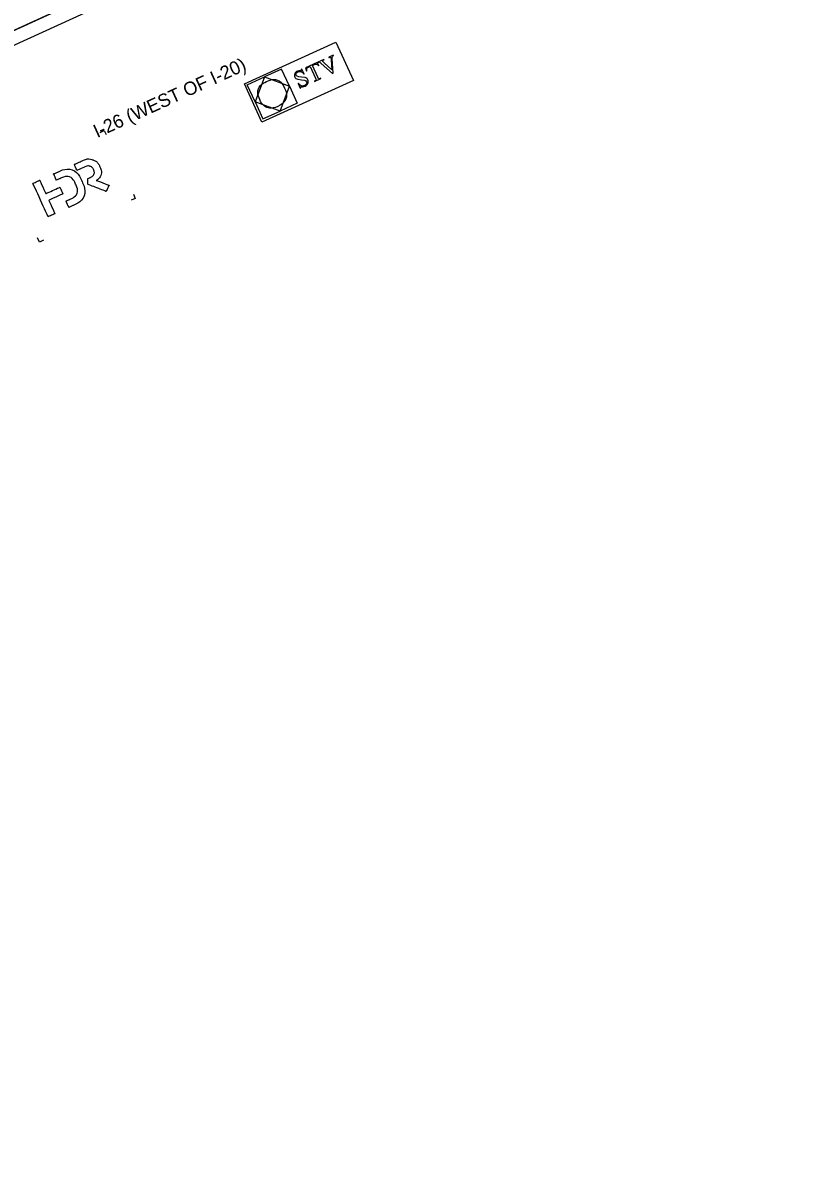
# Model space of a CAD drawing. Extents: x 1952253 to 1982336, y 791177 to 808695.
# Drawn here: x 1973525 to 1979258, y 791177 to 799664 of the extents above; entities that cross this region are included whole.
import ezdxf

# ---------------------------------------------------------------- set-up
doc = ezdxf.new("R2010")
doc.units = 0
for name, color, linetype in [('RD_SHT_Bndy', 7, 'Continuous'), ('RD_SHT_IplotShp', 7, 'Continuous'), ('RD_SHT_Misc2', 7, 'Continuous'), ('RD_SHT_Misc4', 7, 'Continuous'), ('RD_SHT_TX', 7, 'Continuous')]:
    doc.layers.add(name, color=color, linetype=linetype)

msp = doc.modelspace()

# ---------------------------------------------------------------- linework, layer by layer
at = {"layer": 'RD_SHT_Bndy'}
for points in [[(1979125.3, 802195.5), (1955294.1, 791309), (1952385.5, 797676.1), (1976216.7, 808562.6)], [(1959270.9, 793125.7), (1973897.5, 799807.4), (1973461.2, 800762.4), (1958834.7, 794080.8)]]:
    msp.add_lwpolyline(points, close=True, dxfattribs=at)
at = {"layer": 'RD_SHT_IplotShp'}
msp.add_lwpolyline([(1979257.8, 802146.1), (1955244.7, 791176.5), (1952253, 797725.5), (1976266.1, 808695.1)], close=True, dxfattribs=at)
at = {"layer": 'RD_SHT_Misc2'}
for points in [[(1974102.6, 798845.3), (1974133.3, 798859.3), (1974147.3, 798828.6)], [(1974350.4, 798384.1), (1974364.4, 798353.4), (1974333.7, 798339.4)], [(1973680.7, 798041.1), (1973650.1, 798027.1), (1973636, 798057.8)]]:
    msp.add_lwpolyline(points, dxfattribs=at)
for points in [[(1973930.1, 798561.3), (1973930.1, 798561.3), (1973986.4, 798587), (1973986.4, 798587), (1973986.4, 798587), (1974003.4, 798594.8), (1974016.6, 798596.5), (1974028.6, 798592.1), (1974028.6, 798592.1), (1974039.6, 798588.1), (1974048, 798580.1), (1974053.1, 798569), (1974053.1, 798569), (1974064.6, 798543.8), (1974049.7, 798518.8), (1974025.4, 798507.7), (1974025.4, 798507.7), (1974025.4, 798507.7), (1974011.4, 798501.3), (1974011.4, 798501.3), (1974011.4, 798501.3), (1974011.4, 798501.3), (1974011.1, 798458.1), (1974011.1, 798458.1), (1974011.1, 798458.1), (1974011.1, 798458.1), (1974147, 798404.6), (1974147, 798404.6), (1974147, 798404.6), (1974147, 798404.6), (1974169.2, 798451.1), (1974169.2, 798451.1), (1974169.2, 798451.1), (1974169.2, 798451.1), (1974073.6, 798487.2), (1974073.6, 798487.2), (1974073.6, 798487.2), (1974106.7, 798510.4), (1974116.2, 798554.7), (1974100.4, 798589.4), (1974100.4, 798589.4), (1974088.5, 798615.5), (1974071.9, 798632.1), (1974045.4, 798641.1), (1974045.4, 798641.1), (1974017.9, 798650.4), (1973994.6, 798645), (1973962.4, 798630.3), (1973962.4, 798630.3), (1973962.4, 798630.3), (1973909.5, 798606.2), (1973909.5, 798606.2), (1973909.5, 798606.2), (1973909.5, 798606.2), (1973930.1, 798561.3), (1973930.1, 798561.3)], [(1973966.6, 798481.5), (1973966.6, 798481.5), (1973966.5, 798481.6), (1973966.5, 798481.6), (1973966.5, 798481.6), (1973966.5, 798481.6), (1973966.5, 798481.6), (1973966.5, 798481.6), (1973966.5, 798481.6), (1973933.4, 798553.8), (1973857, 798582.2), (1973784.7, 798549.2), (1973784.7, 798549.2), (1973784.7, 798549.2), (1973755.2, 798535.7), (1973755.2, 798535.7), (1973755.2, 798535.7), (1973755.2, 798535.7), (1973776.6, 798488.8), (1973776.6, 798488.8), (1973776.6, 798488.8), (1973776.6, 798488.8), (1973806.1, 798502.3), (1973806.1, 798502.3), (1973806.1, 798502.3), (1973852, 798523.2), (1973898.7, 798505.9), (1973919.7, 798460.1), (1973919.7, 798460.1), (1973940.5, 798414.2), (1973923.2, 798367.3), (1973877.4, 798346.3), (1973877.4, 798346.3), (1973877.4, 798346.3), (1973847.8, 798332.8), (1973847.8, 798332.8), (1973847.8, 798332.8), (1973847.8, 798332.8), (1973869.3, 798286), (1973869.3, 798286), (1973869.3, 798286), (1973869.3, 798286), (1973898.8, 798299.4), (1973898.8, 798299.4), (1973898.8, 798299.4), (1973971, 798332.5), (1973999.4, 798409.1), (1973966.6, 798481.4), (1973966.6, 798481.4), (1973966.6, 798481.4), (1973966.6, 798481.4), (1973966.6, 798481.4), (1973966.6, 798481.4), (1973966.6, 798481.4), (1973966.6, 798481.5), (1973966.6, 798481.5)], [(1973802.1, 798436.4), (1973802.1, 798436.4), (1973697.1, 798388.4), (1973697.1, 798388.4), (1973697.1, 798388.4), (1973697.1, 798388.4), (1973651.5, 798488.3), (1973651.5, 798488.3), (1973651.5, 798488.3), (1973651.5, 798488.3), (1973600.8, 798465.2), (1973600.8, 798465.2), (1973600.8, 798465.2), (1973600.8, 798465.2), (1973714.9, 798215.5), (1973714.9, 798215.5), (1973714.9, 798215.5), (1973714.9, 798215.5), (1973765.5, 798238.6), (1973765.5, 798238.6), (1973765.5, 798238.6), (1973765.5, 798238.6), (1973719.9, 798338.5), (1973719.9, 798338.5), (1973719.9, 798338.5), (1973719.9, 798338.5), (1973824.9, 798386.5), (1973824.9, 798386.5), (1973824.9, 798386.5), (1973824.9, 798386.5), (1973802.1, 798436.4), (1973802.1, 798436.4)]]:
    msp.add_open_spline(points, degree=3, dxfattribs=at)
at = {"layer": 'RD_SHT_Misc4'}
for points in [[(1975178.8, 799208.1), (1975860.9, 799519.7), (1975991.7, 799233.5), (1975309.5, 798921.8)], [(1975841.2, 799421.6), (1975808.2, 799406.5), (1975809.2, 799404.3), (1975810.7, 799404.6), (1975815.9, 799405.6), (1975819.9, 799405.2), (1975824.3, 799401.8), (1975826.4, 799387.2), (1975831.3, 799313.4), (1975773.6, 799364), (1975764.3, 799374.9), (1975763.6, 799377.7), (1975764.3, 799380.6), (1975767.2, 799383.8), (1975772.9, 799387.7), (1975771.8, 799389.9), (1975726.7, 799369.3), (1975727.7, 799367), (1975736.5, 799368.6), (1975743.3, 799366.6), (1975752, 799359.1), (1975836.8, 799284.6), (1975841, 799286.5), (1975833.9, 799394.8), (1975833.8, 799404.1), (1975835.4, 799411.3), (1975837.9, 799415.4), (1975842.3, 799419.4)], [(1975607.6, 799317.6), (1975605.2, 799316.6), (1975605.6, 799310.1), (1975602.7, 799307.1), (1975595.1, 799306.4), (1975583.9, 799305.4), (1975574.2, 799302.4), (1975567.5, 799298.7), (1975562.2, 799294.3), (1975557.7, 799289.1), (1975554.6, 799283.1), (1975552.6, 799276.8), (1975551.9, 799270.7), (1975552.5, 799264.6), (1975554.6, 799258.7), (1975558.3, 799252.6), (1975563.4, 799247.8), (1975569.8, 799244.1), (1975577.5, 799241.7), (1975603.6, 799238.4), (1975625.7, 799236), (1975636, 799231.2), (1975642.1, 799223.8), (1975643.9, 799216), (1975642.2, 799207.9), (1975637.1, 799200.6), (1975628.7, 799195.1), (1975619.8, 799192.2), (1975610.8, 799191.6), (1975602.3, 799193.2), (1975595.3, 799196.6), (1975588.7, 799202.7), (1975581.4, 799212), (1975579.1, 799210.9), (1975595.8, 799174.6), (1975598, 799175.5), (1975597.2, 799181.9), (1975599.8, 799184.7), (1975611.1, 799186.3), (1975622.8, 799187.8), (1975632.1, 799191.2), (1975639.1, 799195), (1975644.8, 799199.7), (1975649.4, 799205.1), (1975652.7, 799211.4), (1975654.7, 799218), (1975655.4, 799224.5), (1975654.7, 799230.9), (1975652.6, 799237.1), (1975648.9, 799243.2), (1975643.9, 799248.3), (1975637.9, 799252.3), (1975630.9, 799254.8), (1975604.3, 799258.2), (1975584.7, 799260.5), (1975572.8, 799264), (1975568.2, 799267.2), (1975565, 799271.8), (1975563.5, 799278.8), (1975565.2, 799286.3), (1975569.6, 799293.1), (1975576.7, 799298), (1975584.5, 799300.4), (1975593, 799300.8), (1975601.3, 799299.1), (1975608.6, 799295.3), (1975615.3, 799289.1), (1975621.9, 799280.1), (1975624.1, 799281.2)], [(1975720.3, 799366.4), (1975633.7, 799326.8), (1975642, 799302.6), (1975645.1, 799304), (1975643.2, 799311.1), (1975643.2, 799317.2), (1975644.6, 799322.3), (1975647.4, 799326.2), (1975657.4, 799332), (1975669.9, 799337.8), (1975709.5, 799251.2), (1975712.5, 799243.5), (1975713.1, 799238.7), (1975710.5, 799233.7), (1975704.9, 799229.9), (1975700.9, 799228), (1975701.9, 799225.8), (1975749.7, 799247.6), (1975748.8, 799249.9), (1975744.8, 799248.1), (1975738.7, 799246.3), (1975733.5, 799247), (1975729.8, 799250.6), (1975725.4, 799258.5), (1975685.9, 799345.1), (1975701.5, 799352.3), (1975707.9, 799354.4), (1975713.5, 799355.1), (1975718.5, 799354), (1975723.3, 799351.2), (1975730.2, 799342.8), (1975733.1, 799344.2)]]:
    msp.add_lwpolyline(points, close=True, dxfattribs=at)
for points in [[(1975514.4, 799190.6), (1975456, 799318.4), (1975328, 799259.9), (1975514.4, 799190.6)], [(1975258.2, 799073.6), (1975199.8, 799201.3), (1975327.8, 799259.8), (1975258.2, 799073.6)], [(1975514.5, 799190.4), (1975572.9, 799062.6), (1975444.8, 799004.1), (1975514.5, 799190.4)], [(1975258.3, 799073.3), (1975316.7, 798945.6), (1975444.7, 799004), (1975258.3, 799073.3)]]:
    msp.add_lwpolyline(points, dxfattribs=at)
msp.add_open_spline([(1975428.5, 799039.4), (1975479.6, 799062.8), (1975502.2, 799123.2), (1975478.8, 799174.4), (1975455.4, 799225.5), (1975395, 799248), (1975343.9, 799224.7), (1975292.7, 799201.3), (1975270.2, 799140.9), (1975293.6, 799089.7), (1975317, 799038.6), (1975377.4, 799016.1), (1975428.5, 799039.4)], degree=3, dxfattribs=at)

# ---------------------------------------------------------------- texts
at = {"layer": 'RD_SHT_TX'}
msp.add_text('I-26 (WEST OF I-20)', height=100, rotation=24.55175, dxfattribs=at).set_placement((1974080.3, 798802.3))

doc.saveas('drawing.dxf')
